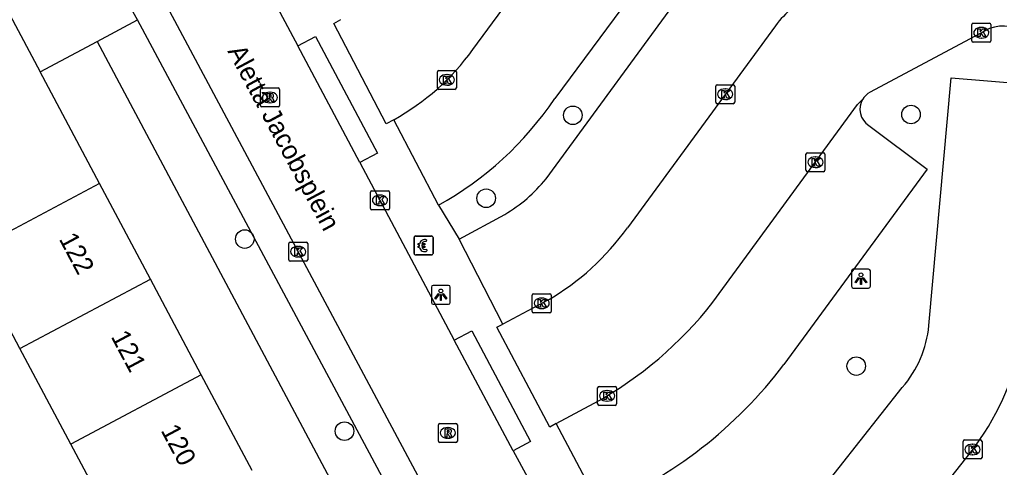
# Model space of a CAD drawing. Extents: x 160304 to 160954, y 383686 to 384161.
# Drawn here: x 160780.3 to 160831.9, y 383832.2 to 383855.8 of the extents above; entities that cross this region are included whole.
import ezdxf

# ---------------------------------------------------------------- set-up
doc = ezdxf.new("R2010")
doc.units = 0
for name, color, linetype in [('IMGEO_Betaalautomaat', 7, 'Continuous'), ('IMGEO_Boom', 7, 'Continuous'), ('IMGEO_Kolk', 7, 'Continuous'), ('IMGEO_Lichtpunt', 7, 'Continuous'), ('IMGEO_Openbare_ruimte_label', 7, 'Continuous'), ('IMGEO_Pand', 7, 'Continuous'), ('IMGEO_Pand_nummerreeks', 7, 'Continuous'), ('IMGEO_Parkeervlak_open', 7, 'Continuous'), ('IMGEO_Rijbaan_lokaal_open', 7, 'Continuous'), ('IMGEO_Rioolput', 7, 'Continuous'), ('IMGEO_Voetpad_open', 7, 'Continuous')]:
    doc.layers.add(name, color=color, linetype=linetype)

msp = doc.modelspace()

# ---------------------------------------------------------------- linework, layer by layer
at = {"layer": 'IMGEO_Betaalautomaat'}
for p, q in [((160801.148, 383844.371), (160801.989, 383844.371)), ((160801.989, 383844.371), (160801.148, 383844.371)), ((160802.072, 383844.297), (160802.072, 383843.456)), ((160802.072, 383843.456), (160802.072, 383844.297)), ((160801.073, 383843.447), (160801.073, 383844.288)), ((160801.073, 383844.288), (160801.073, 383843.447)), ((160801.356, 383843.835), (160801.356, 383843.903)), ((160801.477, 383843.903), (160801.477, 383843.835)), ((160801.735, 383844.176), (160801.718, 383844.076)), ((160801.998, 383843.372), (160801.157, 383843.372)), ((160801.157, 383843.372), (160801.998, 383843.372)), ((160801.722, 383843.67), (160801.744, 383843.583))]:
    msp.add_line(p, q, dxfattribs=at)
for points in [[(160801.356, 383843.903), (160801.287, 383843.903), (160801.287, 383843.972), (160801.366, 383843.972)], [(160801.361, 383843.766), (160801.287, 383843.766), (160801.287, 383843.835), (160801.356, 383843.835)], [(160801.488, 383843.972), (160801.635, 383843.972), (160801.635, 383843.903), (160801.477, 383843.903)], [(160801.477, 383843.835), (160801.635, 383843.835), (160801.635, 383843.766), (160801.491, 383843.766)]]:
    msp.add_lwpolyline(points, dxfattribs=at)
for centre, radius, start, end in [((160801.151, 383844.294), 0.0779, 92.4484, 184.2845), ((160801.151, 383844.294), 0.0779, 92.4484, 184.2845), ((160801.995, 383844.294), 0.0779, 2.4484, 94.2845), ((160801.995, 383844.294), 0.0779, 2.4484, 94.2845), ((160801.649, 383843.896), 0.293, 73.014, 165.0139), ((160801.655, 383843.909), 0.179, 69.3236, 159.5683), ((160801.151, 383843.45), 0.0779, 182.4484, 274.2845), ((160801.151, 383843.45), 0.0779, 182.4484, 274.2845), ((160801.622, 383843.821), 0.267, 191.8096, 297.0389), ((160801.655, 383843.836), 0.179, 202.7625, 291.8693), ((160801.995, 383843.45), 0.0779, 272.4484, 4.2845), ((160801.995, 383843.45), 0.0779, 272.4484, 4.2845)]:
    msp.add_arc(centre, radius, start, end, dxfattribs=at)
at = {"layer": 'IMGEO_Boom'}
for centre in [(160809.447, 383850.734), (160827.287, 383850.775), (160804.876, 383846.36), (160792.141, 383844.21), (160824.397, 383837.514), (160797.401, 383834.086)]:
    msp.add_circle(centre, 0.489, dxfattribs=at)
at = {"layer": 'IMGEO_Kolk'}
for p, q in [((160830.494, 383854.659), (160830.494, 383855.511)), ((160830.569, 383855.585), (160831.421, 383855.585)), ((160830.982, 383855.365), (160831.007, 383855.365)), ((160831.495, 383855.511), (160831.495, 383854.659)), ((160831.005, 383854.805), (160830.98, 383854.805)), ((160831.421, 383854.585), (160830.569, 383854.585)), ((160802.378, 383853.1), (160803.23, 383853.1)), ((160802.303, 383852.174), (160802.303, 383853.026)), ((160802.791, 383852.88), (160802.816, 383852.88)), ((160803.304, 383853.026), (160803.304, 383852.174)), ((160803.23, 383852.1), (160802.378, 383852.1)), ((160802.814, 383852.32), (160802.789, 383852.32)), ((160816.986, 383851.419), (160816.986, 383852.271)), ((160817.061, 383852.345), (160817.913, 383852.345)), ((160817.474, 383852.125), (160817.499, 383852.125)), ((160817.987, 383852.271), (160817.987, 383851.419)), ((160817.497, 383851.565), (160817.472, 383851.565)), ((160817.913, 383851.345), (160817.061, 383851.345)), ((160821.745, 383847.835), (160821.745, 383848.687)), ((160821.82, 383848.761), (160822.672, 383848.761)), ((160822.233, 383848.541), (160822.258, 383848.541)), ((160822.746, 383848.687), (160822.746, 383847.835)), ((160822.256, 383847.981), (160822.231, 383847.981)), ((160822.672, 383847.761), (160821.82, 383847.761)), ((160798.773, 383845.826), (160798.773, 383846.678)), ((160798.848, 383846.752), (160799.7, 383846.752)), ((160799.261, 383846.532), (160799.286, 383846.532)), ((160799.774, 383846.678), (160799.774, 383845.826)), ((160799.284, 383845.972), (160799.259, 383845.972)), ((160799.7, 383845.752), (160798.848, 383845.752)), ((160794.459, 383843.119), (160794.459, 383843.971)), ((160794.534, 383844.045), (160795.386, 383844.045)), ((160794.947, 383843.825), (160794.972, 383843.825)), ((160795.46, 383843.971), (160795.46, 383843.119)), ((160794.97, 383843.265), (160794.945, 383843.265)), ((160795.386, 383843.045), (160794.534, 383843.045)), ((160807.305, 383840.397), (160807.305, 383841.249)), ((160807.38, 383841.323), (160808.232, 383841.323)), ((160808.306, 383841.249), (160808.306, 383840.397)), ((160807.793, 383841.103), (160807.818, 383841.103)), ((160808.232, 383840.323), (160807.38, 383840.323)), ((160807.816, 383840.543), (160807.791, 383840.543)), ((160810.755, 383835.52), (160810.755, 383836.372)), ((160810.83, 383836.446), (160811.682, 383836.446)), ((160811.243, 383836.226), (160811.268, 383836.226)), ((160811.756, 383836.372), (160811.756, 383835.52)), ((160811.266, 383835.666), (160811.241, 383835.666)), ((160811.682, 383835.446), (160810.83, 383835.446)), ((160830.03, 383832.694), (160830.03, 383833.546)), ((160830.105, 383833.62), (160830.957, 383833.62)), ((160831.031, 383833.546), (160831.031, 383832.694)), ((160830.518, 383833.4), (160830.543, 383833.4)), ((160830.957, 383832.62), (160830.105, 383832.62)), ((160830.541, 383832.84), (160830.516, 383832.84))]:
    msp.add_line(p, q, dxfattribs=at)
for points in [[(160830.494, 383854.659), (160830.494, 383855.511)], [(160830.569, 383855.585), (160831.421, 383855.585)], [(160830.815, 383855.285), (160830.938, 383855.285), (160830.938, 383855.134), (160831.068, 383855.285), (160831.232, 383855.285), (160831.086, 383855.134), (160831.239, 383854.885), (160831.087, 383854.885), (160831.002, 383855.049), (160830.938, 383854.982), (160830.938, 383854.885), (160830.815, 383854.885), (160830.815, 383855.285)], [(160831.495, 383855.511), (160831.495, 383854.659)], [(160831.421, 383854.585), (160830.569, 383854.585)], [(160802.378, 383853.1), (160803.23, 383853.1)], [(160802.303, 383852.174), (160802.303, 383853.026)], [(160802.624, 383852.8), (160802.747, 383852.8), (160802.747, 383852.649), (160802.877, 383852.8), (160803.041, 383852.8), (160802.895, 383852.649), (160803.048, 383852.4), (160802.896, 383852.4), (160802.811, 383852.564), (160802.747, 383852.497), (160802.747, 383852.4), (160802.624, 383852.4), (160802.624, 383852.8)], [(160803.304, 383853.026), (160803.304, 383852.174)], [(160803.23, 383852.1), (160802.378, 383852.1)], [(160816.986, 383851.419), (160816.986, 383852.271)], [(160817.061, 383852.345), (160817.913, 383852.345)], [(160817.307, 383852.045), (160817.43, 383852.045), (160817.43, 383851.894), (160817.56, 383852.045), (160817.724, 383852.045), (160817.578, 383851.894), (160817.731, 383851.645), (160817.579, 383851.645), (160817.494, 383851.809), (160817.43, 383851.742), (160817.43, 383851.645), (160817.307, 383851.645), (160817.307, 383852.045)], [(160817.987, 383852.271), (160817.987, 383851.419)], [(160817.913, 383851.345), (160817.061, 383851.345)], [(160821.745, 383847.835), (160821.745, 383848.687)], [(160821.82, 383848.761), (160822.672, 383848.761)], [(160822.066, 383848.461), (160822.189, 383848.461), (160822.189, 383848.31), (160822.319, 383848.461), (160822.483, 383848.461), (160822.337, 383848.31), (160822.49, 383848.061), (160822.338, 383848.061), (160822.253, 383848.225), (160822.189, 383848.158), (160822.189, 383848.061), (160822.066, 383848.061), (160822.066, 383848.461)], [(160822.746, 383848.687), (160822.746, 383847.835)], [(160822.672, 383847.761), (160821.82, 383847.761)], [(160798.773, 383845.826), (160798.773, 383846.678)], [(160798.848, 383846.752), (160799.7, 383846.752)], [(160799.094, 383846.452), (160799.217, 383846.452), (160799.217, 383846.301), (160799.347, 383846.452), (160799.511, 383846.452), (160799.365, 383846.301), (160799.518, 383846.052), (160799.366, 383846.052), (160799.281, 383846.216), (160799.217, 383846.149), (160799.217, 383846.052), (160799.094, 383846.052), (160799.094, 383846.452)], [(160799.774, 383846.678), (160799.774, 383845.826)], [(160799.7, 383845.752), (160798.848, 383845.752)], [(160794.459, 383843.119), (160794.459, 383843.971)], [(160794.534, 383844.045), (160795.386, 383844.045)], [(160795.46, 383843.971), (160795.46, 383843.119)], [(160794.78, 383843.745), (160794.903, 383843.745), (160794.903, 383843.594), (160795.033, 383843.745), (160795.197, 383843.745), (160795.051, 383843.594), (160795.204, 383843.345), (160795.052, 383843.345), (160794.967, 383843.509), (160794.903, 383843.442), (160794.903, 383843.345), (160794.78, 383843.345), (160794.78, 383843.745)], [(160795.386, 383843.045), (160794.534, 383843.045)], [(160807.305, 383840.397), (160807.305, 383841.249)], [(160807.38, 383841.323), (160808.232, 383841.323)], [(160808.306, 383841.249), (160808.306, 383840.397)], [(160807.626, 383841.023), (160807.749, 383841.023), (160807.749, 383840.872), (160807.879, 383841.023), (160808.043, 383841.023), (160807.897, 383840.872), (160808.05, 383840.623), (160807.898, 383840.623), (160807.813, 383840.787), (160807.749, 383840.72), (160807.749, 383840.623), (160807.626, 383840.623), (160807.626, 383841.023)], [(160808.232, 383840.323), (160807.38, 383840.323)], [(160810.755, 383835.52), (160810.755, 383836.372)], [(160810.83, 383836.446), (160811.682, 383836.446)], [(160811.076, 383836.146), (160811.199, 383836.146), (160811.199, 383835.995), (160811.329, 383836.146), (160811.493, 383836.146), (160811.347, 383835.995), (160811.5, 383835.746), (160811.348, 383835.746), (160811.263, 383835.91), (160811.199, 383835.843), (160811.199, 383835.746), (160811.076, 383835.746), (160811.076, 383836.146)], [(160811.756, 383836.372), (160811.756, 383835.52)], [(160811.682, 383835.446), (160810.83, 383835.446)], [(160830.03, 383832.694), (160830.03, 383833.546)], [(160830.105, 383833.62), (160830.957, 383833.62)], [(160831.031, 383833.546), (160831.031, 383832.694)], [(160830.351, 383833.32), (160830.474, 383833.32), (160830.474, 383833.169), (160830.604, 383833.32), (160830.768, 383833.32), (160830.622, 383833.169), (160830.775, 383832.92), (160830.623, 383832.92), (160830.538, 383833.084), (160830.474, 383833.017), (160830.474, 383832.92), (160830.351, 383832.92), (160830.351, 383833.32)], [(160830.957, 383832.62), (160830.105, 383832.62)]]:
    msp.add_lwpolyline(points, dxfattribs=at)
for centre, start, end in [((160830.571, 383855.509), 91.552, 178.448), ((160830.571, 383855.509), 91.552, 178.448), ((160831.419, 383855.509), 1.552, 88.448), ((160831.419, 383855.509), 1.552, 88.448), ((160830.571, 383854.661), 181.552, 268.448), ((160830.571, 383854.661), 181.552, 268.448), ((160831.419, 383854.661), 271.552, 358.448), ((160831.419, 383854.661), 271.552, 358.448), ((160802.38, 383853.024), 91.552, 178.448), ((160802.38, 383853.024), 91.552, 178.448), ((160803.228, 383853.024), 1.552, 88.448), ((160803.228, 383853.024), 1.552, 88.448), ((160802.38, 383852.176), 181.552, 268.448), ((160802.38, 383852.176), 181.552, 268.448), ((160803.228, 383852.176), 271.552, 358.448), ((160803.228, 383852.176), 271.552, 358.448), ((160817.063, 383852.269), 91.552, 178.448), ((160817.063, 383852.269), 91.552, 178.448), ((160817.911, 383852.269), 1.552, 88.448), ((160817.911, 383852.269), 1.552, 88.448), ((160817.063, 383851.421), 181.552, 268.448), ((160817.063, 383851.421), 181.552, 268.448), ((160817.911, 383851.421), 271.552, 358.448), ((160817.911, 383851.421), 271.552, 358.448), ((160821.822, 383848.685), 91.552, 178.448), ((160821.822, 383848.685), 91.552, 178.448), ((160822.67, 383848.685), 1.552, 88.448), ((160822.67, 383848.685), 1.552, 88.448), ((160821.822, 383847.837), 181.552, 268.448), ((160821.822, 383847.837), 181.552, 268.448), ((160822.67, 383847.837), 271.552, 358.448), ((160822.67, 383847.837), 271.552, 358.448), ((160798.85, 383846.676), 91.552, 178.448), ((160798.85, 383846.676), 91.552, 178.448), ((160799.698, 383846.676), 1.552, 88.448), ((160799.698, 383846.676), 1.552, 88.448), ((160798.85, 383845.828), 181.552, 268.448), ((160798.85, 383845.828), 181.552, 268.448), ((160799.698, 383845.828), 271.552, 358.448), ((160799.698, 383845.828), 271.552, 358.448), ((160794.536, 383843.969), 91.552, 178.448), ((160794.536, 383843.969), 91.552, 178.448), ((160795.384, 383843.969), 1.552, 88.448), ((160795.384, 383843.969), 1.552, 88.448), ((160794.536, 383843.121), 181.552, 268.448), ((160794.536, 383843.121), 181.552, 268.448), ((160795.384, 383843.121), 271.552, 358.448), ((160795.384, 383843.121), 271.552, 358.448), ((160807.382, 383841.247), 91.552, 178.448), ((160807.382, 383841.247), 91.552, 178.448), ((160808.23, 383841.247), 1.552, 88.448), ((160808.23, 383841.247), 1.552, 88.448), ((160807.382, 383840.399), 181.552, 268.448), ((160807.382, 383840.399), 181.552, 268.448), ((160808.23, 383840.399), 271.552, 358.448), ((160808.23, 383840.399), 271.552, 358.448), ((160810.832, 383836.37), 91.552, 178.448), ((160810.832, 383836.37), 91.552, 178.448), ((160811.68, 383836.37), 1.552, 88.448), ((160811.68, 383836.37), 1.552, 88.448), ((160810.832, 383835.522), 181.552, 268.448), ((160810.832, 383835.522), 181.552, 268.448), ((160811.68, 383835.522), 271.552, 358.448), ((160811.68, 383835.522), 271.552, 358.448), ((160830.107, 383833.544), 91.552, 178.448), ((160830.107, 383833.544), 91.552, 178.448), ((160830.955, 383833.544), 1.552, 88.448), ((160830.955, 383833.544), 1.552, 88.448), ((160830.107, 383832.696), 181.552, 268.448), ((160830.107, 383832.696), 181.552, 268.448), ((160830.955, 383832.696), 271.552, 358.448), ((160830.955, 383832.696), 271.552, 358.448)]:
    msp.add_arc(centre, 0.0765, start, end, dxfattribs=at)
for centre, major_axis, ratio, start_param, end_param in [((160830.981, 383855.085), (-0.387, 0.002), 0.722429, 4.712389, 7.853982), ((160831.006, 383855.085), (-0.39, 0.002), 0.717154, 1.570796, 4.712389), ((160802.79, 383852.6), (-0.387, 0.002), 0.722429, 4.712389, 7.853982), ((160802.815, 383852.6), (-0.39, 0.002), 0.717154, 1.570796, 4.712389), ((160817.473, 383851.845), (-0.387, 0.002), 0.722429, 4.712389, 7.853982), ((160817.498, 383851.845), (-0.39, 0.002), 0.717154, 1.570796, 4.712389), ((160822.232, 383848.261), (-0.387, 0.002), 0.722429, 4.712389, 7.853982), ((160822.257, 383848.261), (-0.39, 0.002), 0.717154, 1.570796, 4.712389), ((160799.26, 383846.252), (-0.387, 0.002), 0.722429, 4.712389, 7.853982), ((160799.285, 383846.252), (-0.39, 0.002), 0.717154, 1.570796, 4.712389), ((160794.946, 383843.545), (-0.387, 0.002), 0.722429, 4.712389, 7.853982), ((160794.971, 383843.545), (-0.39, 0.002), 0.717154, 1.570796, 4.712389), ((160807.792, 383840.823), (-0.387, 0.002), 0.722429, 4.712389, 7.853982), ((160807.817, 383840.823), (-0.39, 0.002), 0.717154, 1.570796, 4.712389), ((160811.242, 383835.946), (-0.387, 0.002), 0.722429, 4.712389, 7.853982), ((160811.267, 383835.946), (-0.39, 0.002), 0.717154, 1.570796, 4.712389), ((160830.517, 383833.12), (-0.387, 0.002), 0.722429, 4.712389, 7.853982), ((160830.542, 383833.12), (-0.39, 0.002), 0.717154, 1.570796, 4.712389)]:
    msp.add_ellipse(centre, major_axis=major_axis, ratio=ratio, start_param=start_param, end_param=end_param, dxfattribs=at)
at = {"layer": 'IMGEO_Lichtpunt'}
for p, q in [((160824.147, 383842.528), (160824.147, 383841.721)), ((160824.147, 383842.528), (160824.147, 383841.721)), ((160825.049, 383842.623), (160824.241, 383842.623)), ((160825.049, 383842.623), (160824.241, 383842.623)), ((160825.143, 383841.721), (160825.143, 383842.528)), ((160825.143, 383841.721), (160825.143, 383842.528)), ((160802.888, 383841.771), (160802.08, 383841.771)), ((160802.888, 383841.771), (160802.08, 383841.771)), ((160801.986, 383841.676), (160801.986, 383840.869)), ((160801.986, 383841.676), (160801.986, 383840.869)), ((160802.982, 383840.869), (160802.982, 383841.676)), ((160802.982, 383840.869), (160802.982, 383841.676)), ((160824.241, 383841.627), (160825.049, 383841.627)), ((160824.241, 383841.627), (160825.049, 383841.627)), ((160802.08, 383840.775), (160802.888, 383840.775)), ((160802.08, 383840.775), (160802.888, 383840.775))]:
    msp.add_line(p, q, dxfattribs=at)
for points in [[(160824.521, 383842.192), (160824.56, 383842.164), (160824.372, 383841.902), (160824.334, 383841.929), (160824.521, 383842.192)], [(160824.623, 383842.144), (160824.67, 383842.144), (160824.67, 383841.822), (160824.623, 383841.822), (160824.623, 383842.144)], [(160824.733, 383842.164), (160824.771, 383842.191), (160824.958, 383841.929), (160824.919, 383841.901), (160824.733, 383842.164)], [(160802.36, 383841.34), (160802.399, 383841.312), (160802.211, 383841.05), (160802.173, 383841.077), (160802.36, 383841.34)], [(160802.462, 383841.292), (160802.509, 383841.292), (160802.509, 383840.97), (160802.462, 383840.97), (160802.462, 383841.292)], [(160802.572, 383841.312), (160802.61, 383841.339), (160802.797, 383841.077), (160802.758, 383841.049), (160802.572, 383841.312)]]:
    msp.add_lwpolyline(points, dxfattribs=at)
for centre in [(160824.646, 383842.326), (160802.485, 383841.474)]:
    msp.add_circle(centre, 0.0994, dxfattribs=at)
for centre, start, end in [((160824.241, 383842.528), 90, 180), ((160824.241, 383842.528), 90, 180), ((160825.049, 383842.528), 0, 90), ((160825.049, 383842.528), 0, 90), ((160802.08, 383841.676), 90, 180), ((160802.08, 383841.676), 90, 180), ((160802.888, 383841.676), 0, 90), ((160802.888, 383841.676), 0, 90), ((160824.241, 383841.721), 180, 270), ((160824.241, 383841.721), 180, 270), ((160825.049, 383841.721), 270, 0), ((160825.049, 383841.721), 270, 360), ((160802.08, 383840.869), 180, 270), ((160802.08, 383840.869), 180, 270), ((160802.888, 383840.869), 270, 0), ((160802.888, 383840.869), 270, 360)]:
    msp.add_arc(centre, 0.0946, start, end, dxfattribs=at)
at = {"layer": 'IMGEO_Pand'}
for points in [[(160772.352, 383855.702), (160775.444, 383857.347), (160776.688, 383856.968), (160778.409, 383856.443), (160779.749, 383856.033), (160781.345, 383853.033)], [(160784.479, 383847.144), (160781.345, 383853.033)], [(160784.479, 383847.144), (160777.597, 383843.482)], [(160787.163, 383842.1), (160784.479, 383847.144)], [(160780.281, 383838.438), (160777.597, 383843.482)], [(160780.281, 383838.438), (160787.163, 383842.1)], [(160789.847, 383837.056), (160787.163, 383842.1)], [(160782.966, 383833.394), (160780.281, 383838.438)], [(160789.847, 383837.056), (160782.966, 383833.394)], [(160792.531, 383832.012), (160789.847, 383837.056)], [(160785.65, 383828.349), (160782.966, 383833.394)]]:
    msp.add_lwpolyline(points, dxfattribs=at)
at = {"layer": 'IMGEO_Parkeervlak_open'}
for points in [[(160828.226, 383839.655), (160829.406, 383852.716), (160833.443, 383852.383)], [(160825.061, 383850.193), (160828.145, 383847.893), (160820.58, 383837.604)], [(160818.697, 383819.974), (160815.741, 383822.324), (160826.826, 383836.393)]]:
    msp.add_lwpolyline(points, dxfattribs=at)
for centre, radius, start, end in [((160825.607, 383851.052), 1.018, 148.2983, 237.5588), ((160822.584, 383840.145), 5.663, 318.5062, 355.0373), ((160801.876, 383851.692), 23.416, 292.6652, 323.0134)]:
    msp.add_arc(centre, radius, start, end, dxfattribs=at)
at = {"layer": 'IMGEO_Rijbaan_lokaal_open'}
for points in [[(160788.396, 383867.631), (160788.408, 383867.485), (160788.499, 383866.959), (160788.636, 383866.444), (160788.819, 383865.943), (160788.947, 383865.656), (160792.495, 383858.988), (160794.942, 383854.39)], [(160804.168, 383854.193), (160811.286, 383863.857)], [(160785.169, 383861.857), (160809.333, 383816.673)], [(160800.003, 383850.5), (160799.597, 383850.284), (160796.835, 383855.575), (160797.216, 383855.79)], [(160820.132, 383855.449), (160812.325, 383844.809)], [(160831.418, 383855.311), (160825.135, 383851.954), (160825.011, 383851.878)], [(160798.216, 383848.237), (160794.942, 383854.39)], [(160816.832, 383840.884), (160824.472, 383851.296), (160824.741, 383851.587)], [(160798.216, 383848.237), (160803.196, 383838.878)], [(160808.122, 383840.989), (160805.747, 383839.727)], [(160808.576, 383834.484), (160808.226, 383834.297), (160805.439, 383839.563), (160805.747, 383839.727)], [(160806.296, 383833.052), (160803.196, 383838.878)], [(160808.576, 383834.484), (160810.58, 383835.559)], [(160806.296, 383833.052), (160815.679, 383815.845)], [(160830.683, 383833.311), (160819.095, 383818.648)]]:
    msp.add_lwpolyline(points, dxfattribs=at)
for centre, radius, start, end in [((160824.978, 383851.824), 6.051, 118.4722, 143.2051), ((160832.155, 383853.195), 2.24, 358.0184, 109.209), ((160793.75, 383861.748), 12.869, 299.0725, 324.0526), ((160825.611, 383851.05), 1.023, 125.9531, 148.3345), ((160801.448, 383852.555), 13.353, 299.9881, 324.5457), ((160800.725, 383853.462), 20.436, 298.8305, 322.0134), ((160819.84, 383841.321), 13.481, 323.5441, 351.3034)]:
    msp.add_arc(centre, radius, start, end, dxfattribs=at)
at = {"layer": 'IMGEO_Rioolput'}
for p, q in [((160792.969, 383851.247), (160792.969, 383852.099)), ((160793.044, 383852.173), (160793.896, 383852.173)), ((160793.97, 383852.099), (160793.97, 383851.247)), ((160793.457, 383851.953), (160793.482, 383851.953)), ((160793.896, 383851.173), (160793.044, 383851.173)), ((160793.48, 383851.393), (160793.455, 383851.393)), ((160802.43, 383834.491), (160803.282, 383834.491)), ((160802.355, 383833.565), (160802.355, 383834.417)), ((160802.843, 383834.271), (160802.868, 383834.271)), ((160803.356, 383834.417), (160803.356, 383833.565)), ((160803.282, 383833.491), (160802.43, 383833.491)), ((160802.866, 383833.711), (160802.841, 383833.711))]:
    msp.add_line(p, q, dxfattribs=at)
for points in [[(160792.969, 383851.247), (160792.969, 383852.099)], [(160793.044, 383852.173), (160793.896, 383852.173)], [(160793.97, 383852.099), (160793.97, 383851.247)], [(160793.558, 383851.871), (160793.306, 383851.873), (160793.306, 383851.473)], [(160793.306, 383851.473), (160793.43, 383851.473), (160793.43, 383851.635), (160793.441, 383851.635)], [(160793.484, 383851.792), (160793.43, 383851.792), (160793.43, 383851.711)], [(160793.43, 383851.711), (160793.482, 383851.711)], [(160793.488, 383851.606), (160793.559, 383851.473), (160793.699, 383851.473), (160793.634, 383851.599)], [(160793.896, 383851.173), (160793.044, 383851.173)], [(160802.43, 383834.491), (160803.282, 383834.491)], [(160802.355, 383833.565), (160802.355, 383834.417)], [(160802.944, 383834.189), (160802.692, 383834.191), (160802.692, 383833.791)], [(160802.692, 383833.791), (160802.816, 383833.791), (160802.816, 383833.953), (160802.827, 383833.953)], [(160802.87, 383834.11), (160802.816, 383834.11), (160802.816, 383834.029)], [(160802.816, 383834.029), (160802.868, 383834.029)], [(160803.356, 383834.417), (160803.356, 383833.565)], [(160803.282, 383833.491), (160802.43, 383833.491)], [(160802.874, 383833.924), (160802.945, 383833.791), (160803.085, 383833.791), (160803.02, 383833.917)]]:
    msp.add_lwpolyline(points, dxfattribs=at)
for centre, radius, start, end in [((160793.046, 383852.097), 0.0765, 91.552, 178.448), ((160793.046, 383852.097), 0.0765, 91.552, 178.448), ((160793.894, 383852.097), 0.0765, 1.552, 88.448), ((160793.894, 383852.097), 0.0765, 1.552, 88.448), ((160793.44, 383851.582), 0.0533, 26.0293, 88.6989), ((160793.466, 383851.9), 0.19, 274.7715, 282.9687), ((160793.49, 383851.696), 0.0964, 77.0061, 93.1865), ((160793.504, 383851.753), 0.0378, 276.6634, 79.6772), ((160793.557, 383851.761), 0.109, 350.3612, 89.416), ((160793.555, 383851.761), 0.112, 277.5842, 350.9817), ((160793.539, 383851.546), 0.108, 29.5134, 73.7905), ((160793.046, 383851.249), 0.0765, 181.552, 268.448), ((160793.046, 383851.249), 0.0765, 181.552, 268.448), ((160793.894, 383851.249), 0.0765, 271.552, 358.448), ((160793.894, 383851.249), 0.0765, 271.552, 358.448), ((160802.432, 383834.415), 0.0765, 91.552, 178.448), ((160802.432, 383834.415), 0.0765, 91.552, 178.448), ((160803.28, 383834.415), 0.0765, 1.552, 88.448), ((160803.28, 383834.415), 0.0765, 1.552, 88.448), ((160802.826, 383833.9), 0.0533, 26.0293, 88.6989), ((160802.852, 383834.218), 0.19, 274.7715, 282.9687), ((160802.876, 383834.014), 0.0964, 77.0061, 93.1865), ((160802.89, 383834.071), 0.0378, 276.6634, 79.6772), ((160802.943, 383834.079), 0.109, 350.3612, 89.416), ((160802.941, 383834.079), 0.112, 277.5842, 350.9817), ((160802.925, 383833.864), 0.108, 29.5134, 73.7905), ((160802.432, 383833.567), 0.0765, 181.552, 268.448), ((160802.432, 383833.567), 0.0765, 181.552, 268.448), ((160803.28, 383833.567), 0.0765, 271.552, 358.448), ((160803.28, 383833.567), 0.0765, 271.552, 358.448)]:
    msp.add_arc(centre, radius, start, end, dxfattribs=at)
for centre, major_axis, ratio, start_param, end_param in [((160793.456, 383851.673), (-0.387, 0.002), 0.722429, 4.712389, 7.853982), ((160793.481, 383851.673), (-0.39, 0.002), 0.717154, 1.570796, 4.712389), ((160802.842, 383833.991), (-0.387, 0.002), 0.722429, 4.712389, 7.853982), ((160802.867, 383833.991), (-0.39, 0.002), 0.717154, 1.570796, 4.712389)]:
    msp.add_ellipse(centre, major_axis=major_axis, ratio=ratio, start_param=start_param, end_param=end_param, dxfattribs=at)
at = {"layer": 'IMGEO_Voetpad_open'}
for points in [[(160815.155, 383860.61), (160808.494, 383851.615)], [(160786.477, 383855.764), (160784.614, 383859.091)], [(160808.033, 383847.388), (160815.584, 383857.703)], [(160784.351, 383854.625), (160786.477, 383855.764)], [(160806.317, 383818.739), (160786.477, 383855.764)], [(160794.942, 383854.39), (160795.869, 383854.884), (160799.143, 383848.731), (160798.216, 383848.237)], [(160781.345, 383853.033), (160784.351, 383854.625)], [(160784.351, 383854.625), (160801.546, 383822.346), (160798.507, 383820.783)], [(160802.356, 383845.996), (160800.003, 383850.5)], [(160802.356, 383845.996), (160803.446, 383844.206)], [(160803.446, 383844.206), (160805.86, 383845.511)], [(160805.747, 383839.727), (160803.446, 383844.206)], [(160803.196, 383838.878), (160804.123, 383839.372), (160807.223, 383833.546), (160806.296, 383833.052)], [(160810.899, 383830.084), (160808.576, 383834.484)]]:
    msp.add_lwpolyline(points, dxfattribs=at)
for centre, radius, start, end in [((160793.804, 383861.5), 17.707, 298.8817, 326.063), ((160801.909, 383852.281), 7.839, 300.2664, 321.3734)]:
    msp.add_arc(centre, radius, start, end, dxfattribs=at)

# ---------------------------------------------------------------- texts
at = {"layer": 'IMGEO_Openbare_ruimte_label'}
msp.add_text('Aletta Jacobsplein', height=1, rotation=298.1533, dxfattribs=at).set_placement((160791.214, 383854.118))
at = {"layer": 'IMGEO_Pand_nummerreeks'}
for s, p in [('122', (160782.32, 383844.22)), ('121', (160785.059, 383839.072)), ('120', (160787.692, 383834.126))]:
    msp.add_text(s, height=1, rotation=298.0189, dxfattribs=at).set_placement(p)

doc.saveas('drawing.dxf')
